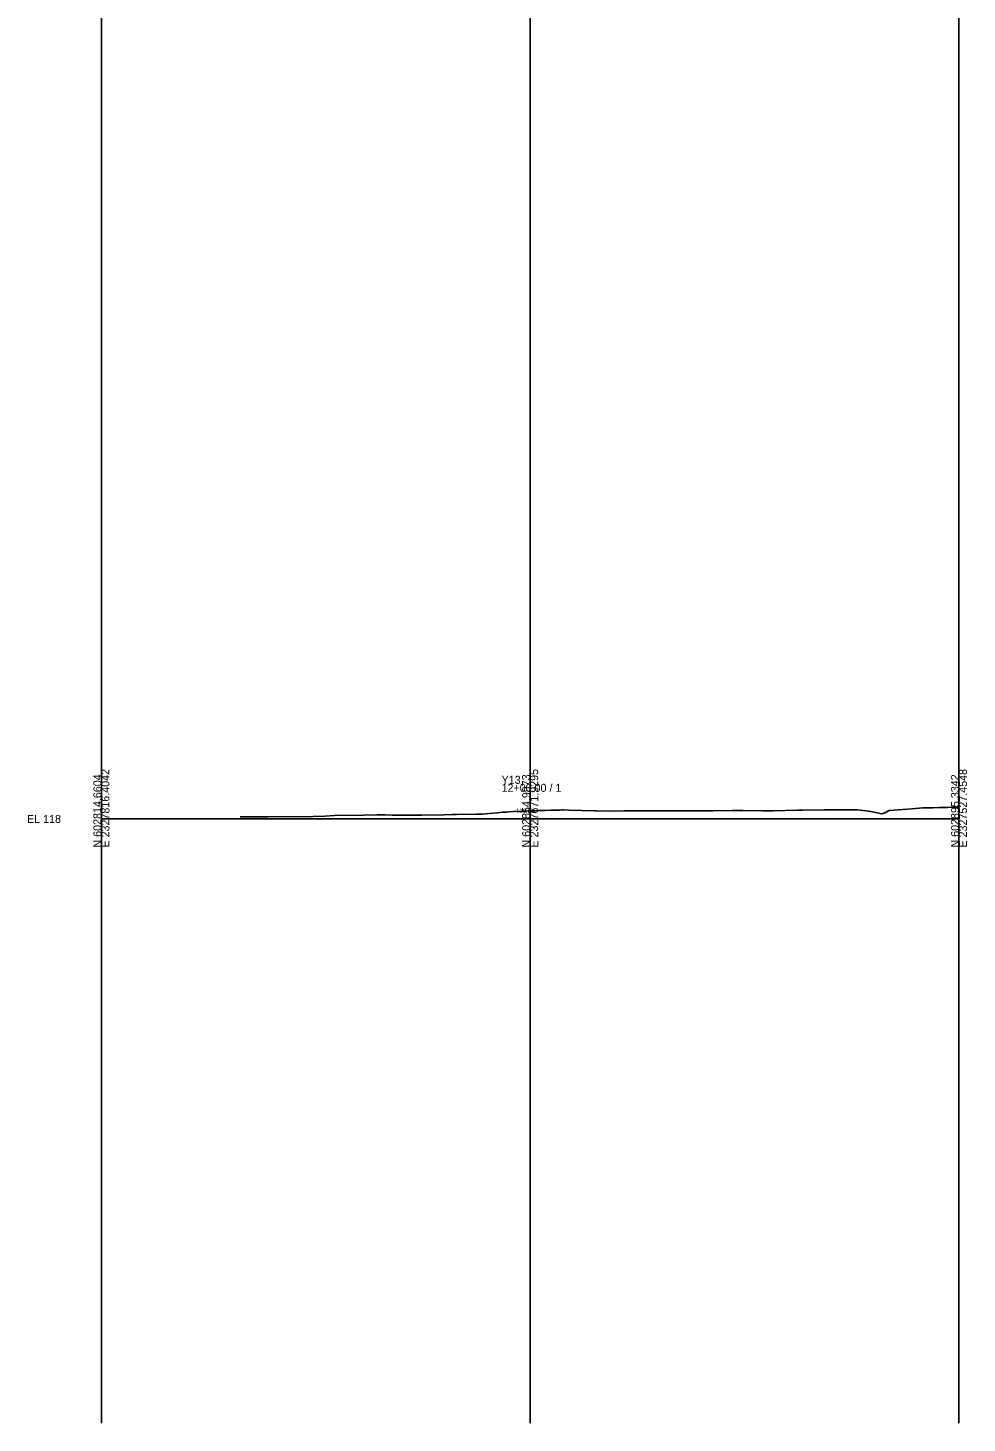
# Model space of a CAD drawing. Extents: x -26 to 1603, y -711 to 1241.
# Drawn here: x -25.7 to 302.8, y -711.4 to -223.2 of the extents above; entities that cross this region are included whole.
import ezdxf

# ---------------------------------------------------------------- set-up
doc = ezdxf.new("R2010")
doc.units = 0
for name, color, linetype in [('Exist CMT Pavement', 7, 'Continuous'), ('Exist Cross Section Cell', 7, 'Continuous'), ('Exist XS Center Line Elevation Label', 7, 'Continuous'), ('Exist XS Ground Line', 7, 'Continuous'), ('Prop XS Earthwork Shape', 7, 'Continuous'), ('Scratch_Level_9', 7, 'Continuous')]:
    doc.layers.add(name, color=color, linetype=linetype)

msp = doc.modelspace()

# ---------------------------------------------------------------- linework, layer by layer
at = {"layer": 'Exist CMT Pavement'}
for p, q in [((149.9, -497.06), (149.9, -497.26)), ((150, -497.06), (149.9, -497.06)), ((149.9, -497.26), (150, -497.26)), ((150.1, -497.06), (150, -497.06)), ((150, -497.26), (150.1, -497.26)), ((150.1, -497.26), (150.1, -497.06))]:
    msp.add_line(p, q, dxfattribs=at)
at = {"layer": 'Exist Cross Section Cell'}
for p, q in [((150, -500), (150, -487.7)), ((0, -500), (150, -500)), ((150, -500), (300, -500))]:
    msp.add_line(p, q, dxfattribs=at)
at = {"layer": 'Exist XS Ground Line'}
msp.add_lwpolyline([(48.56, -499.24), (57.68, -499.26), (58.31, -499.26), (74.08, -499.11), (78.23, -499.04), (81.6, -498.74), (91.74, -498.62), (96.43, -498.57), (99.33, -498.61), (101.9, -498.64), (103.88, -498.66), (105.35, -498.68), (106.49, -498.69), (107.43, -498.7), (108.22, -498.71), (112.12, -498.69), (119.75, -498.52), (122.72, -498.43), (124.22, -498.4), (131.02, -498.29), (133.28, -498.34), (134.5, -498.17), (135.65, -498.04), (138.56, -497.82), (139.39, -497.71), (140.37, -497.65), (141.63, -497.58), (142.7, -497.52), (144.2, -497.44), (147.11, -497.29), (149.44, -497.17), (150.06, -497.16), (150.98, -497.14), (151.92, -497.11), (153.05, -497.08), (154.49, -497.04), (155.11, -497.02), (157.18, -496.95), (157.65, -496.94), (159.25, -496.89), (159.64, -496.89), (160.39, -496.87), (161.03, -496.86), (161.79, -496.85), (163.54, -496.89), (172.56, -497.14), (173.15, -497.15), (179.94, -497.24), (182.92, -497.19), (188.21, -497.15), (193.3, -497.12), (202.61, -497.15), (203.68, -497.16), (206.45, -497.17), (212.41, -497.19), (214.07, -497.2), (220.52, -497.06), (224.45, -497.03), (231.43, -497.16), (234.84, -497.19), (243.64, -496.98), (244.87, -496.94), (245.22, -496.94), (252.99, -496.78), (256.62, -496.78), (264.4, -496.86), (267.54, -497.15), (268.38, -497.23), (269.15, -497.4), (273.01, -498.18), (274.03, -497.82), (275.54, -497.09), (280.41, -496.67), (283.66, -496.41), (287.3, -496.12), (287.64, -496.12), (288.69, -496.07), (290.89, -496.06), (293.07, -496.01), (293.7, -495.99), (294.67, -495.98), (296.03, -495.95), (297.83, -495.93), (298.61, -495.91), (300, -495.9)], dxfattribs=at)
at = {"layer": 'Prop XS Earthwork Shape'}
msp.add_lwpolyline([(149.9, -497.16), (150.06, -497.16), (150.1, -497.15), (150.1, -497.26), (150, -497.26), (149.9, -497.26)], close=True, dxfattribs=at)
at = {"layer": 'Scratch_Level_9'}
for p, q in [((0, 1241.32), (0, -711.39)), ((150, 1241.32), (150, -711.39)), ((300, 1241.32), (300, -711.39))]:
    msp.add_line(p, q, dxfattribs=at)

# ---------------------------------------------------------------- texts
at = {"layer": 'Exist Cross Section Cell'}
for s, p in [('E 2327816.4042', (2.8, -510)), ('E 2327671.9295', (152.8, -510)), ('E 2327527.4548', (302.8, -510)), ('N 602814.6604', (0, -510)), ('N 602854.9973', (150, -510)), ('N 602895.3342', (300, -510))]:
    msp.add_text(s, height=2.8, rotation=90, dxfattribs=at).set_placement(p)
for s, p in [('Y13', (140, -487.7)), ('12+00.00 / 1', (140, -490.5)), ('EL 118', (-26, -501.4))]:
    msp.add_text(s, height=2.8, dxfattribs=at).set_placement(p)
at = {"layer": 'Exist XS Center Line Elevation Label'}
msp.add_text('120.84', height=1.5, dxfattribs=at).set_placement((145.07, -497.91))

doc.saveas('drawing.dxf')
